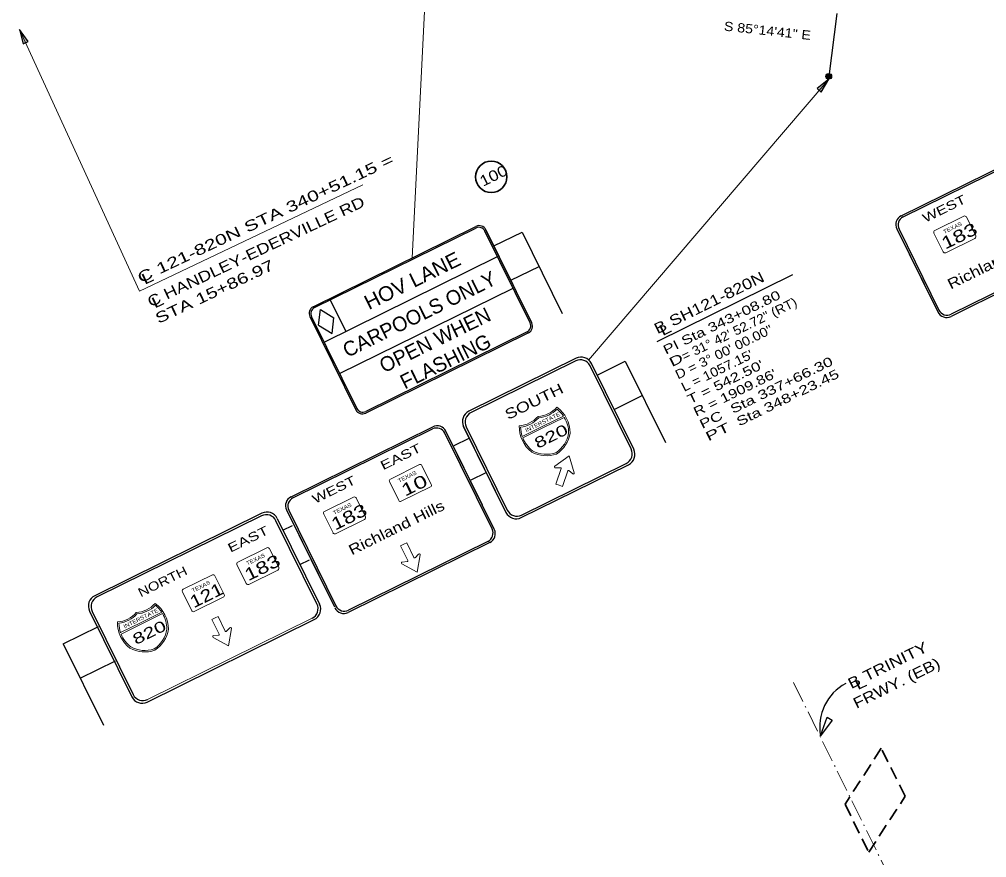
# Model space of a CAD drawing. Extents: x 2356431 to 2371438, y 6972864 to 6982525.
# Drawn here: x 2361693 to 2362955, y 6976537 to 6977631 of the extents above; entities that cross this region are included whole.
import ezdxf
from ezdxf.enums import TextEntityAlignment as Align

# ---------------------------------------------------------------- set-up
doc = ezdxf.new("R2010")
doc.units = 0
doc.header["$LTSCALE"] = 5.6
doc.linetypes.add('DOT_DASHED', pattern=[7.7, 5, -1.2, 0.3, -1.2])
doc.linetypes.add('MEDIUM_DASHED', pattern=[4.5, 3, -1.5])
for name, color, linetype, lineweight in [('1', 7, 'Continuous', 25), ('17', 7, 'Continuous', 35), ('2', 7, 'Continuous', 35), ('28', 7, 'Continuous', 35), ('44', 7, 'Continuous', 13), ('48', 7, 'Continuous', 25), ('53', 7, 'Continuous', 13), ('61', 7, 'Continuous', 13)]:
    doc.layers.add(name, color=color, linetype=linetype, lineweight=lineweight)
doc.layers.add('25', color=7, linetype='Continuous')
doc.layers.add('33', color=7, linetype='Continuous')

msp = doc.modelspace()

# ---------------------------------------------------------------- hatches: boundary and pattern name
at = {"layer": '48'}
for points in [[(2361692.72, 6977618.159), (2361697.68, 6977599.257), (2361704.186, 6977602.342)], [(2362749.369, 6977553.002), (2362733.96, 6977540.993), (2362739.369, 6977536.225)], [(2362752.134, 6977554.771, 1), (2362745.964, 6977558.97, 1)]]:
    msp.add_hatch(color=256, dxfattribs=at).paths.add_polyline_path(points)

# ---------------------------------------------------------------- linework, layer by layer
at = {"layer": '1', "lineweight": 13}
for p, q in [((2361878.636, 6976857.494), (2361851.735, 6976844.214)), ((2361879.644, 6976855.879), (2361852.574, 6976842.521)), ((2361824.836, 6976830.936), (2361851.735, 6976844.214)), ((2361825.486, 6976829.146), (2361852.574, 6976842.521))]:
    msp.add_line(p, q, dxfattribs=at)
for centre, radius, start, end in [((2361843.146, 6976893.135), 35.984, 273.44845, 318.29876), ((2361843.146, 6976893.135), 37.874, 274.64636, 315.6432), ((2361845.254, 6976835.327), 41.954, 0.13125, 53.83362), ((2361845.254, 6976835.327), 40.064, 33.57769, 51.44245), ((2361818.117, 6976880.783), 35.984, 274.23736, 319.08768), ((2361818.117, 6976880.783), 37.874, 276.89292, 317.88976), ((2361845.254, 6976835.327), 40.064, 0.34779, 30.85977), ((2361862.719, 6976843.947), 41.954, 178.7025, 232.40488), ((2361862.719, 6976843.947), 40.064, 181.09368, 198.95843), ((2361862.719, 6976843.947), 40.064, 201.67636, 232.18834), ((2361847.014, 6976841.807), 38.808, 304.1061, 350.75248), ((2361847.014, 6976841.807), 40.698, 303.73996, 350.97586), ((2361856.505, 6976846.491), 40.698, 241.56027, 288.79617), ((2361856.505, 6976846.491), 38.808, 241.78364, 288.43003)]:
    msp.add_arc(centre, radius, start, end, dxfattribs=at)
at = {"layer": '17'}
msp.add_circle((2362308.523, 6977425.716), 20.576, dxfattribs=at)
at = {"layer": '2', "lineweight": 25}
msp.add_lwpolyline([(2362753.584, 6976716.808), (2362738.281, 6976696.3), (2362747.109, 6976720.548)], close=True, dxfattribs=at)
at = {"layer": '2', "linetype": 'MEDIUM_DASHED'}
msp.add_lwpolyline([(2362770.318, 6976606.986), (2362801.228, 6976544.356), (2362848.87, 6976617.514), (2362817.651, 6976680.013)], close=True, dxfattribs=at)
at = {"layer": '2', "lineweight": 25}
msp.add_arc((2362802.152, 6976707.793), 64.896, 118.54585, 190.20091, dxfattribs=at)
at = {"layer": '44', "linetype": 'DOT_DASHED'}
msp.add_line((2362702.943, 6976766.1), (2362854.642, 6976458.725), dxfattribs=at)
at = {"layer": '48', "lineweight": 13}
for p, q in [((2362205.326, 6977319.927), (2362226.507, 6977743.821)), ((2361692.72, 6977618.159), (2361849.671, 6977276.606)), ((2362749.369, 6977553.002), (2362435.305, 6977186.607)), ((2362141.026, 6977415.307), (2361849.671, 6977276.606)), ((2362925.444, 6977374.425), (2362887.422, 6977355.667)), ((2362940.859, 6977348.669), (2362928.69, 6977373.327)), ((2362886.322, 6977352.424), (2362898.491, 6977327.766)), ((2362901.738, 6977326.66), (2362939.754, 6977345.421)), ((2362402.934, 6977113.457), (2362376.037, 6977100.175)), ((2362403.951, 6977111.832), (2362376.874, 6977098.485)), ((2362349.124, 6977086.902), (2362376.037, 6977100.175)), ((2362349.78, 6977085.109), (2362376.874, 6977098.485)), ((2362214.947, 6977050.162), (2362176.925, 6977031.389)), ((2362230.37, 6977024.401), (2362218.195, 6977049.07)), ((2362175.818, 6977028.157), (2362187.991, 6977003.493)), ((2362191.243, 6977002.389), (2362229.261, 6977021.159)), ((2362129.021, 6977007.761), (2362090.999, 6976989.003)), ((2362144.436, 6976982.005), (2362132.267, 6977006.663)), ((2362089.899, 6976985.76), (2362102.068, 6976961.101)), ((2362105.315, 6976959.996), (2362143.331, 6976978.757)), ((2362015.839, 6976941.677), (2361977.817, 6976922.919)), ((2362031.254, 6976915.921), (2362019.085, 6976940.579)), ((2361976.717, 6976919.676), (2361988.886, 6976895.018)), ((2361944.595, 6976906.287), (2361906.573, 6976887.529)), ((2361960.01, 6976880.531), (2361947.841, 6976905.189)), ((2361992.133, 6976893.912), (2362030.149, 6976912.673)), ((2361905.473, 6976884.286), (2361917.642, 6976859.628)), ((2361920.889, 6976858.522), (2361958.905, 6976877.283)), ((2361860.072, 6976743.741), (2362074.763, 6976849.688))]:
    msp.add_line(p, q, dxfattribs=at)
at = {"layer": '48'}
for p, q in [((2362759.58, 6977638.842), (2362749.046, 6977556.87)), ((2362843.723, 6977375.028), (2363028.65, 6977466.288)), ((2362846.238, 6977373.582), (2363028.257, 6977463.422)), ((2362076.211, 6977256.207), (2362288.68, 6977361.063)), ((2362078.072, 6977255.136), (2362288.39, 6977358.94)), ((2362359.385, 6977235.331), (2362300.406, 6977354.862)), ((2362301.481, 6977356.721), (2362336.668, 6977285.428)), ((2362361.522, 6977235.053), (2362301.481, 6977356.721)), ((2362311.939, 6977335.532), (2362348.798, 6977353.724)), ((2362348.797, 6977353.723), (2362401.238, 6977247.468)), ((2362837.857, 6977357.726), (2362885.559, 6977261.07)), ((2362837.857, 6977357.726), (2362885.559, 6977261.07)), ((2362837.857, 6977357.726), (2362891.309, 6977249.408)), ((2362840.744, 6977357.35), (2362892.761, 6977251.922)), ((2363093.53, 6977334.816), (2362908.612, 6977243.538)), ((2363091.003, 6977336.271), (2362908.984, 6977246.431)), ((2362090.325, 6977210.048), (2362316.726, 6977321.792)), ((2362334.07, 6977290.695), (2362370.928, 6977308.885)), ((2362110.614, 6977168.929), (2362337.02, 6977280.673)), ((2362098.386, 6977265.164), (2362118.681, 6977224.043)), ((2362083.245, 6977232.018), (2362085.571, 6977252.519)), ((2362085.571, 6977252.519), (2362103.257, 6977241.892)), ((2362071.869, 6977243.398), (2362131.911, 6977121.726)), ((2362074.005, 6977243.12), (2362132.99, 6977123.591)), ((2362100.933, 6977221.391), (2362103.257, 6977241.892)), ((2362083.245, 6977232.018), (2362100.933, 6977221.391)), ((2362357.182, 6977222.252), (2362144.72, 6977117.383)), ((2362355.312, 6977223.329), (2362144.997, 6977119.524)), ((2362419.235, 6977188.912), (2362279.334, 6977119.896)), ((2362418.8, 6977185.555), (2362282.263, 6977118.182)), ((2362494.544, 6977070.202), (2362439.314, 6977182.1)), ((2362446.71, 6977167.117), (2362483.568, 6977185.309)), ((2362483.568, 6977185.308), (2362536.009, 6977079.053)), ((2362491.181, 6977070.639), (2362437.631, 6977179.178)), ((2362468.84, 6977122.28), (2362505.698, 6977140.47)), ((2362047.3, 6977008.364), (2362232.226, 6977099.624)), ((2362049.814, 6977006.918), (2362231.834, 6977096.758)), ((2362297.074, 6976997.405), (2362249.52, 6977093.76)), ((2362312.611, 6976965.923), (2362249.52, 6977093.76)), ((2362327.535, 6976988.018), (2362272.305, 6977099.916)), ((2362272.514, 6977099.789), (2362327.72, 6976987.892)), ((2362275.885, 6977099.345), (2362329.418, 6976990.829)), ((2362309.728, 6976966.309), (2362248.066, 6977091.248)), ((2362260.274, 6977075.103), (2362279.912, 6977084.795)), ((2362347.828, 6976981.088), (2362487.723, 6977050.11)), ((2362348.263, 6976984.443), (2362484.787, 6977051.807)), ((2362282.401, 6977030.269), (2362302.033, 6977039.957)), ((2362009.211, 6976986.793), (2361791.152, 6976879.182)), ((2362008.776, 6976983.436), (2361794.078, 6976877.49)), ((2362041.434, 6976991.062), (2362089.136, 6976894.406)), ((2362041.434, 6976991.062), (2362089.136, 6976894.406)), ((2362041.434, 6976991.062), (2362103.812, 6976864.667)), ((2362044.321, 6976990.686), (2362105.973, 6976865.734)), ((2362081.157, 6976868.52), (2362027.607, 6976977.059)), ((2362029.305, 6976979.972), (2362084.513, 6976868.083)), ((2362036.789, 6976964.802), (2362049.175, 6976970.915)), ((2362306.741, 6976948.628), (2362121.823, 6976857.351)), ((2362304.216, 6976950.083), (2362122.196, 6976860.243)), ((2362058.909, 6976919.973), (2362071.298, 6976926.088)), ((2361784.331, 6976859.096), (2361839.537, 6976747.199)), ((2361787.702, 6976858.652), (2361841.235, 6976750.136)), ((2361859.635, 6976740.389), (2362077.699, 6976847.991)), ((2361750.045, 6976816.336), (2361795.917, 6976838.976)), ((2361750.045, 6976816.336), (2361802.486, 6976710.081)), ((2361772.175, 6976771.496), (2361818.042, 6976794.133))]:
    msp.add_line(p, q, dxfattribs=at)
for points in [[(2361692.72, 6977618.159), (2361697.68, 6977599.257), (2361704.186, 6977602.342)], [(2362749.369, 6977553.002), (2362733.96, 6977540.993), (2362739.369, 6977536.225)]]:
    msp.add_lwpolyline(points, close=True, dxfattribs=at)
msp.add_circle((2362749.049, 6977556.87), 3.732, dxfattribs=at)
for centre, radius, start, end in [((2362849.44, 6977363.445), 12.919, 116.26456, 206.26456), ((2362851.603, 6977362.711), 12.111, 116.26456, 206.26456), ((2362292.367, 6977350.886), 8.966, 26.26515, 116.26515), ((2362292.91, 6977352.487), 9.563, 26.26515, 116.26515), ((2362080.443, 6977247.631), 9.563, 116.26456, 206.26456), ((2362082.044, 6977247.088), 8.966, 116.26456, 206.26456), ((2362902.893, 6977255.124), 12.919, 206.26456, 296.26456), ((2362903.627, 6977257.287), 12.111, 206.26456, 296.26456), ((2362351.345, 6977231.364), 8.966, 296.26515, 26.26515), ((2362352.946, 6977230.821), 9.563, 296.26515, 26.26515), ((2362425.024, 6977172.944), 14.063, 26.26238, 116.26238), ((2362425.875, 6977175.455), 15.001, 26.26237, 116.26237), ((2362140.487, 6977125.959), 9.563, 206.26456, 296.26456), ((2362141.03, 6977127.56), 8.966, 206.26456, 296.26456), ((2362285.972, 6977106.425), 15.001, 116.26237, 206.26237), ((2362288.483, 6977105.573), 14.063, 116.26237, 206.26238), ((2362237.208, 6977085.88), 12.111, 26.26515, 116.26515), ((2362237.941, 6977088.042), 12.919, 26.26515, 116.26515), ((2362478.572, 6977064.418), 14.063, 296.26238, 26.26238), ((2362481.083, 6977063.566), 15.001, 296.26238, 26.26238), ((2362053.017, 6976996.781), 12.919, 116.26456, 206.26456), ((2362055.18, 6976996.047), 12.111, 116.26456, 206.26456), ((2362015.001, 6976970.824), 14.063, 26.26238, 116.26238), ((2362015.853, 6976973.335), 15.001, 26.26237, 116.26237), ((2362341.179, 6976994.536), 15.001, 206.26237, 296.26237), ((2362342.031, 6976997.047), 14.063, 206.26238, 296.26238), ((2362298.856, 6976960.941), 12.111, 296.26515, 26.26515), ((2362301.019, 6976960.208), 12.919, 296.26515, 26.26515), ((2361797.79, 6976865.73), 15.001, 116.26237, 206.26237), ((2361800.301, 6976864.878), 14.063, 116.26237, 206.26238), ((2362068.549, 6976862.297), 14.063, 296.26238, 26.26238), ((2362071.06, 6976861.446), 15.001, 296.26238, 26.26238), ((2362116.105, 6976868.937), 12.919, 206.26456, 296.26456), ((2362116.839, 6976871.099), 12.111, 206.26456, 296.26456), ((2361852.997, 6976753.841), 15.001, 206.26237, 296.26237), ((2361853.849, 6976756.352), 14.063, 206.26238, 296.26238)]:
    msp.add_arc(centre, radius, start, end, dxfattribs=at)
at = {"layer": '48', "lineweight": 13}
for centre, radius, start, end in [((2362926.517, 6977372.261), 2.422, 26.26405, 116.26405), ((2362888.489, 6977353.496), 2.422, 116.26405, 206.26405), ((2362938.686, 6977347.599), 2.422, 296.26405, 26.26405), ((2362900.658, 6977328.835), 2.422, 206.26405, 296.26405), ((2362367.452, 6977149.104), 35.984, 273.44271, 318.29302), ((2362367.452, 6977149.104), 37.874, 274.64062, 315.63746), ((2362369.554, 6977091.295), 41.954, 0.12551, 53.82789), ((2362369.554, 6977091.295), 40.064, 33.57196, 51.43671), ((2362342.422, 6977136.753), 35.984, 274.23163, 319.08194), ((2362342.422, 6977136.753), 37.874, 276.88719, 317.88403), ((2362369.554, 6977091.295), 40.064, 0.34205, 30.85403), ((2362387.02, 6977099.913), 41.954, 178.69676, 232.39914), ((2362387.02, 6977099.913), 40.064, 181.08794, 198.95269), ((2362387.02, 6977099.913), 40.064, 201.67062, 232.1826), ((2362371.315, 6977097.775), 38.808, 304.10036, 350.74674), ((2362371.315, 6977097.775), 40.698, 303.73422, 350.97012), ((2362380.807, 6977102.458), 40.698, 241.55453, 288.79043), ((2362380.807, 6977102.458), 38.808, 241.77791, 288.42429), ((2362216.021, 6977047.991), 2.422, 26.26515, 116.26515), ((2362177.994, 6977029.225), 2.422, 116.26515, 206.26515), ((2362228.191, 6977023.33), 2.422, 296.26515, 26.26515), ((2362130.093, 6977005.596), 2.422, 26.26405, 116.26405), ((2362190.164, 6977004.564), 2.422, 206.26515, 296.26515), ((2362092.066, 6976986.832), 2.422, 116.26405, 206.26405), ((2362142.262, 6976980.935), 2.422, 296.26405, 26.26405), ((2362104.235, 6976962.17), 2.422, 206.26405, 296.26405), ((2362016.912, 6976939.513), 2.422, 26.26405, 116.26405), ((2361978.885, 6976920.748), 2.422, 116.26405, 206.26405), ((2361945.669, 6976904.121), 2.422, 26.26405, 116.26405), ((2362029.081, 6976914.851), 2.422, 296.26405, 26.26405), ((2361991.054, 6976896.087), 2.422, 206.26405, 296.26405), ((2361907.642, 6976885.357), 2.422, 116.26405, 206.26405), ((2361957.838, 6976879.46), 2.422, 296.26405, 26.26405), ((2361919.811, 6976860.695), 2.422, 206.26405, 296.26405)]:
    msp.add_arc(centre, radius, start, end, dxfattribs=at)
at = {"layer": '53'}
for p, q in [((2362392.431, 6977045.963), (2362399.026, 6977046.083)), ((2362399.855, 6977045.015), (2362399.883, 6977045.001)), ((2362409.725, 6977042.4), (2362414.869, 6977038.194)), ((2362198.39, 6976948.289), (2362207.716, 6976928.91)), ((2362209.087, 6976928.751), (2362213.666, 6976933.498)), ((2362192.306, 6976923.129), (2362198.917, 6976923.791)), ((2361962.89, 6976832.699), (2361967.469, 6976837.446)), ((2361969.543, 6976836.379), (2361969.558, 6976836.373)), ((2361946.109, 6976827.077), (2361952.72, 6976827.739))]:
    msp.add_line(p, q, dxfattribs=at)
for points in [[(2362416.751, 6977039.538), (2362410.354, 6977061.654), (2362391.713, 6977048.199)], [(2362399.883, 6977045.001), (2362392.777, 6977024.702), (2362397.051, 6977023.221), (2362401.467, 6977021.708), (2362408.357, 6977042.032)], [(2362199.624, 6976925.019), (2362190.127, 6976944.263), (2362194.321, 6976946.316), (2362198.39, 6976948.289)], [(2362215.755, 6976932.425), (2362212.085, 6976909.73), (2362191.925, 6976920.848)], [(2361953.427, 6976828.967), (2361943.93, 6976848.211), (2361948.124, 6976850.264), (2361952.193, 6976852.237), (2361961.519, 6976832.858)], [(2361969.558, 6976836.373), (2361965.888, 6976813.678), (2361945.728, 6976824.796)]]:
    msp.add_lwpolyline(points, dxfattribs=at)
for centre, radius, start, end in [((2362392.427, 6977047.196), 1.215, 125.62527, 271.00641), ((2362399.089, 6977045.28), 0.81, 340.88678, 90.86988), ((2362409.192, 6977041.779), 0.81, 50.90367, 160.88678), ((2362415.612, 6977039.161), 1.215, 230.76714, 16.14828), ((2362214.541, 6976932.63), 1.215, 350.61782, 135.99896), ((2362192.463, 6976921.919), 1.215, 95.75969, 241.14083), ((2362198.854, 6976924.607), 0.81, 275.89622, 25.87932), ((2362208.474, 6976929.274), 0.81, 205.87932, 315.86243), ((2361952.658, 6976828.555), 0.81, 275.89622, 25.87932), ((2361962.278, 6976833.222), 0.81, 205.87932, 315.86243), ((2361968.345, 6976836.578), 1.215, 350.61782, 135.99896), ((2361946.267, 6976825.867), 1.215, 95.75969, 241.14083)]:
    msp.add_arc(centre, radius, start, end, dxfattribs=at)
at = {"layer": '61', "lineweight": 25}
msp.add_line((2362525.167, 6977210.882), (2362702.124, 6977298.217), dxfattribs=at)

# ---------------------------------------------------------------- texts
at = {"layer": '1'}
for s, height, width, p in [('INTERSTATE', 5.198, 1.15, (2361830.147, 6976836.262)), ('820', 14.18, 1.45, (2361844.942, 6976814.725))]:
    msp.add_text(s, height=height, rotation=26.268, dxfattribs=dict(at, width=width)).set_placement(p)
at = {"layer": '1', "width": 1.4}
msp.add_text('L', height=14, rotation=26.268, dxfattribs=at).set_placement((2362793.456, 6976758.923), align=Align.CENTER)
at = {"layer": '17', "width": 1.2}
msp.add_text('100', height=14, rotation=26.268, dxfattribs=at).set_placement((2362314.717, 6977420.968), align=Align.CENTER)
at = {"layer": '2'}
for s, width, p in [('B TRINITY', 1.25, (2362829.121, 6976782.164)), ('FRWY. (EB)', 1.2, (2362840.628, 6976758.849))]:
    msp.add_text(s, height=14, rotation=26.268, dxfattribs=dict(at, width=width)).set_placement(p, align=Align.CENTER)
at = {"layer": '25'}
for s, width, p in [('C 121-820N STA 340+51.15 =', 1.45, (2361851.049, 6977286.791)), ('C HANDLEY-EDERVILLE RD', 1.25, (2361864.019, 6977255.423)), ('STA 15+86.97', 1.4, (2361874.265, 6977233.718)), ('L', 1.4, (2361856.374, 6977284.719)), ('L', 1.4, (2361869.49, 6977253.832))]:
    msp.add_text(s, height=14, rotation=25.268, dxfattribs=dict(at, width=width)).set_placement(p)
at = {"layer": '28'}
for s, height, rotation, width, p in [('S 85°14\'41" E', 12, 353.784, 1.15, (2362668.439, 6977610.471)), ('B SH121-820N', 14, 26.377, 1.25, (2362595.996, 6977255.168))]:
    msp.add_text(s, height=height, rotation=rotation, dxfattribs=dict(at, width=width)).set_placement(p, align=Align.CENTER)
at = {"layer": '33'}
for s, width, p in [('PI Sta 343+08.80', 1.35, (2362536.512, 6977193.571)), ('= 31° 42\' 52.72" (RT)', 1.1, (2362560.592, 6977185.338)), ('D = 3° 00\' 00.00"', 1.15, (2362552.346, 6977161.263)), ("L = 1057.15'", 1.15, (2362560.263, 6977145.109)), ('D', 1.55, (2362544.429, 6977177.417)), ("T = 542.50'", 1.35, (2362568.181, 6977128.955)), ('Sta 337+66.30', 1.4, (2362624.109, 6977116.331)), ("R = 1909.86'", 1.3, (2362576.098, 6977112.801)), ('Sta 348+23.45', 1.4, (2362632.15, 6977099.925)), ('PC', 1.4, (2362584.015, 6977096.647)), ('PT', 1.6, (2362591.933, 6977080.493))]:
    msp.add_text(s, height=12, rotation=26.11, dxfattribs=dict(at, width=width)).set_placement(p)
at = {"layer": '48'}
for s, height, rotation, width, p in [('WEST', 11.63, 26.264, 1.35, (2362902.165, 6977378.993)), ('Richland Hills', 13.5, 26.27, 1.25, (2362969.503, 6977308.844)), ('HOV LANE', 19.13, 26.264, 1.05, (2362209.752, 6977281.674)), ('SOUTH', 13.5, 26.262, 1.3, (2362367.447, 6977126.544)), ('EAST', 11.63, 26.264, 1.4, (2362192.981, 6977055.386)), ('WEST', 11.63, 26.264, 1.35, (2362105.74, 6977012.329)), ('Richland Hills', 13.5, 26.27, 1.25, (2362187.93, 6976961.925)), ('EAST', 11.63, 26.264, 1.4, (2361993.805, 6976947.781)), ('NORTH', 11.63, 26.264, 1.25, (2361882.204, 6976892.305))]:
    msp.add_text(s, height=height, rotation=rotation, dxfattribs=dict(at, width=width)).set_placement(p, align=Align.CENTER)
for s, height, rotation, width, p in [('183', 16.15, 26.264, 1.35, (2362901.174, 6977330.62)), ('TEXAS', 5.167, 26.264, 1.15, (2362900.026, 6977351.222)), ('INTERSTATE', 5.197, 26.262, 1.15, (2362354.448, 6977092.225)), ('820', 14.18, 26.262, 1.45, (2362369.238, 6977070.695)), ('TEXAS', 5.167, 26.265, 1.15, (2362188.389, 6977026.397)), ('10', 16.15, 26.265, 1.45, (2362196.081, 6977008.202)), ('183', 16.15, 26.264, 1.35, (2362104.75, 6976963.956)), ('TEXAS', 5.167, 26.264, 1.15, (2362103.601, 6976984.559)), ('183', 16.15, 26.264, 1.35, (2361991.568, 6976897.874)), ('TEXAS', 5.167, 26.264, 1.15, (2361990.42, 6976918.476)), ('121', 16.15, 26.264, 1.25, (2361920.322, 6976862.483)), ('TEXAS', 5.167, 26.264, 1.15, (2361919.174, 6976883.085))]:
    msp.add_text(s, height=height, rotation=rotation, dxfattribs=dict(at, width=width)).set_placement(p)
for s, p in [('CARPOOLS ONLY', (2362218.997, 6977237.87)), ('OPEN WHEN', (2362239.369, 6977204.256)), ('FLASHING', (2362253.141, 6977176.344))]:
    msp.add_text(s, height=19.13, rotation=26.264, dxfattribs=at).set_placement(p, align=Align.CENTER)
at = {"layer": '61', "width": 1.4}
msp.add_text('L', height=14, rotation=26.268, dxfattribs=at).set_placement((2362538.658, 6977220.99), align=Align.CENTER)

doc.saveas('drawing.dxf')
